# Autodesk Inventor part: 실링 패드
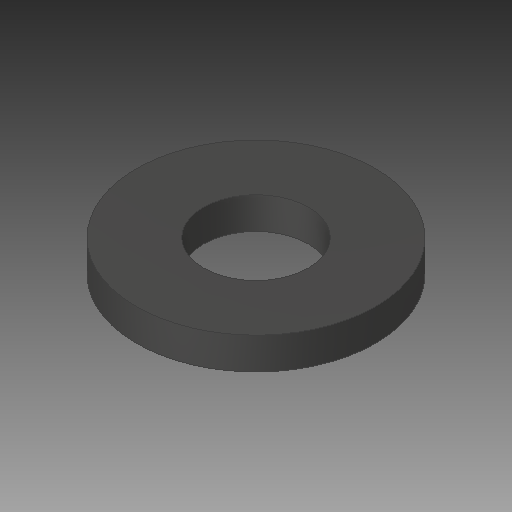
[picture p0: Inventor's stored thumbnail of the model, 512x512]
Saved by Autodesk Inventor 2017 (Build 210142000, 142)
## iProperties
Created: 2024-09
Part Number: 실링 패드
Material: 일반
Document SubType Name: Modeling
Designer: MRC
Density: 1 g/cm^3
Appearance: 기본값
Author: jhkim
Sending System: Autodesk Inventor 2025
Preprocessor: ST-DEVELOPER v20
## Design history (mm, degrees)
feature "솔리드1"
node "솔리드2"
